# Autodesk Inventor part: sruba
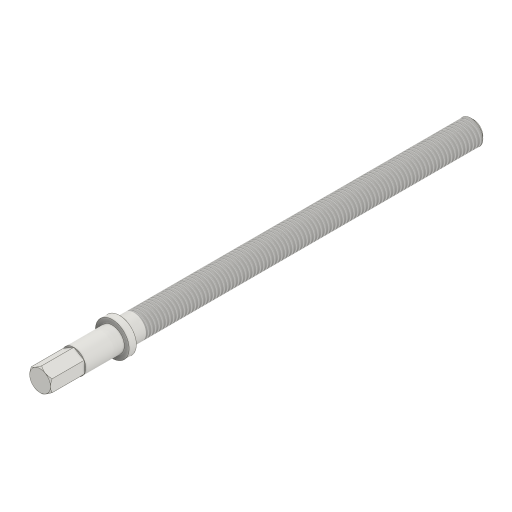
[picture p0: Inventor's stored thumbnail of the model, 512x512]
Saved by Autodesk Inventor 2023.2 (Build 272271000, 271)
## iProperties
Created: 2022-12
Part Number: sruba
Material: Ogólny
Document SubType Name: Modeling
Designer: DOM
Density: 1 g/cm^3
Appearance: Stal
Mass: 12.9879 g
Surface Area: 55.1203 cm^2
Volume: 12.9879 cm^3
Author: DOM
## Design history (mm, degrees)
sketch "Szkic1"
  geometry: C1 r 5 at (0, 0); 1 further point
  constraints: 1 centre point, 1 coincident
  dimensions: "d0" = 10 diameter of C1
extrude "Wyciągnięcie proste1" new body sketch "Szkic1" stored distance "d1" = 150; taper "d2" = 0 deg
chamfer "Faza1" distance "d3" = 1; stored, may be unused: second distance "d4" = 2, angle "d5" = 45 deg
feature "Gwint1" dims "d6" = 140, "d7" = 0
sketch "Szkic2" dims "d25" = 10 (derived)
  geometry: L1 (0, 5)-(4.33, 2.5); L2 (4.33, 2.5)-(4.33, -2.5); L3 (4.33, -2.5)-(0, -5); L4 (0, -5)-(-4.33, -2.5); L5 (-4.33, -2.5)-(-4.33, 2.5); L6 (-4.33, 2.5)-(0, 5); 3 further points
  constraints: 12 end point, 1 coincident, 1 vertical alignment, 14 other
extrude "Wyciągnięcie proste2" join sketch "Szkic2" distance "d8" = 30; taper "d9" = 0 deg
sketch "Szkic3"
  geometry: L1 (-12.6, 0)-(12.6, 0) reference; C1 r 4 at (0, 0) reference; C2 r 7 at (0, 0); 1 further point
  constraints: 1 centre point, 1 coincident
  dimensions: "d24" = 14 diameter of C2
extrude "Wyciągnięcie proste3" join sketch "Szkic3" distance "d12" = 3; taper "d13" = 0 deg
node "Płaszczyzna konstrukcyjna1"
sketch "Szkic5"
  geometry: L1 (2.5, 0)-(0, 0) reference; L2 (0, 30)-(0, 0) reference; L3 (0, 0)-(2.5, 0) reference; L4 (0.68, 0)-(0, 0.68); L5 (5, 216)-(5, -36) reference; 2 further points
  constraints: 2 end point, 2 point on line
  dimensions: "d21" = 0.68 distance of L1.end L4.start; "d22" = 0.68 distance of L4.end L1.end (= d21)
revolve "Obrót2" sketch "Szkic5" stored, may be unused: angle "d23" = 360 deg
sketch "Szkic6"
  geometry: L1 (-4.33, 2.5)-(0, 5) reference; 2 further points
  constraints: 1 coincident, 1 vertical alignment, 2 other
extrude "Wyciągnięcie proste4" join sketch "Szkic6" distance "d26" = 16; taper "d27" = 0 deg
node "Bryła1"
other parameters: "d10" = 18
